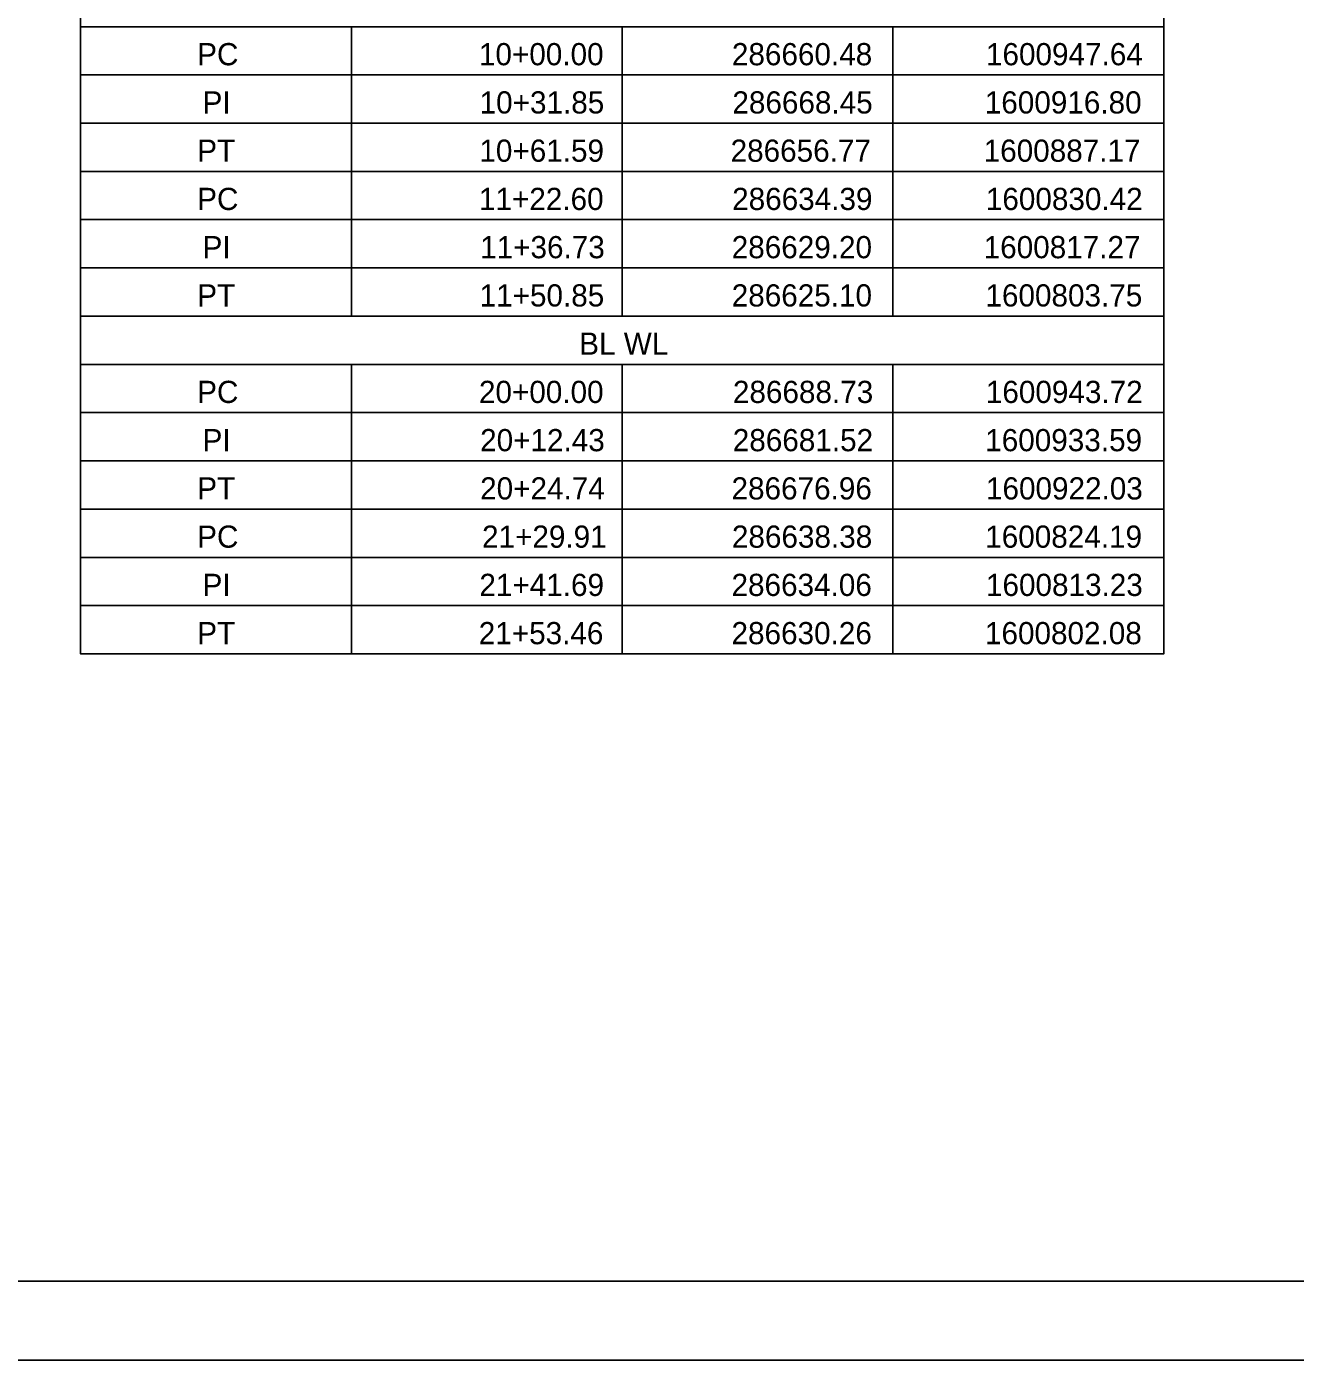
# Model space of a CAD drawing. Extents: x 0 to 34, y 0 to 22.
# Drawn here: x 17 to 25, y 0 to 8.41 of the extents above; entities that cross this region are included whole.
import ezdxf

# ---------------------------------------------------------------- set-up
doc = ezdxf.new("R2010")
doc.units = 0
for name, color, linetype in [('SH_Border', 7, 'Continuous'), ('SH_Cut_Line', 7, 'Continuous'), ('SH_Text', 7, 'Continuous')]:
    doc.layers.add(name, color=color, linetype=linetype)

msp = doc.modelspace()

# ---------------------------------------------------------------- linework, layer by layer
at = {"layer": 'SH_Border'}
msp.add_lwpolyline([(1.5, 21.5), (33.5, 21.5), (33.5, 0.5), (1.5, 0.5)], close=True, dxfattribs=at)
at = {"layer": 'SH_Cut_Line'}
msp.add_lwpolyline([(0, 0), (34, 0), (34, 22), (0, 22)], close=True, dxfattribs=at)
at = {"layer": 'SH_Text'}
for p, q in [((17.3382, 9.0217), (17.3382, 8.1087)), ((24.1691, 9.0217), (24.1691, 8.1087)), ((17.3382, 8.413), (24.1691, 8.413)), ((19.0459, 8.413), (19.0459, 8.1087)), ((20.7536, 8.413), (20.7536, 8.1087)), ((22.4614, 8.413), (22.4614, 8.1087)), ((17.3382, 8.1087), (24.1691, 8.1087)), ((17.3382, 8.1087), (17.3382, 7.8043)), ((19.0459, 8.1087), (19.0459, 7.8043)), ((20.7536, 8.1087), (20.7536, 7.8043)), ((22.4614, 8.1087), (22.4614, 7.8043)), ((24.1691, 8.1087), (24.1691, 7.8043)), ((17.3382, 7.8043), (24.1691, 7.8043)), ((17.3382, 7.8043), (17.3382, 7.1957)), ((19.0459, 7.8043), (19.0459, 7.1957)), ((20.7536, 7.8043), (20.7536, 7.1957)), ((22.4614, 7.8043), (22.4614, 7.1957)), ((24.1691, 7.8043), (24.1691, 7.1957)), ((17.3382, 7.5), (24.1691, 7.5)), ((17.3382, 7.1957), (24.1691, 7.1957)), ((17.3382, 7.1957), (17.3382, 6.8913)), ((19.0459, 7.1957), (19.0459, 6.8913)), ((20.7536, 7.1957), (20.7536, 6.8913)), ((22.4614, 7.1957), (22.4614, 6.8913)), ((24.1691, 7.1957), (24.1691, 6.8913)), ((17.3382, 6.8913), (24.1691, 6.8913)), ((17.3382, 6.8913), (17.3382, 5.9783)), ((19.0459, 6.8913), (19.0459, 6.587)), ((20.7536, 6.8913), (20.7536, 6.587)), ((22.4614, 6.8913), (22.4614, 6.587)), ((24.1691, 6.8913), (24.1691, 5.9783)), ((17.3382, 6.587), (24.1691, 6.587)), ((17.3382, 6.2826), (24.1691, 6.2826)), ((19.0459, 6.2826), (19.0459, 5.9783)), ((20.7536, 6.2826), (20.7536, 5.9783)), ((22.4614, 6.2826), (22.4614, 5.9783)), ((17.3382, 5.9783), (24.1691, 5.9783)), ((17.3382, 5.9783), (17.3382, 5.6739)), ((19.0459, 5.9783), (19.0459, 5.6739)), ((20.7536, 5.9783), (20.7536, 5.6739)), ((22.4614, 5.9783), (22.4614, 5.6739)), ((24.1691, 5.9783), (24.1691, 5.6739)), ((17.3382, 5.6739), (24.1691, 5.6739)), ((17.3382, 5.6739), (17.3382, 5.0652)), ((19.0459, 5.6739), (19.0459, 5.0652)), ((20.7536, 5.6739), (20.7536, 5.0652)), ((22.4614, 5.6739), (22.4614, 5.0652)), ((24.1691, 5.6739), (24.1691, 5.0652)), ((17.3382, 5.3696), (24.1691, 5.3696)), ((17.3382, 5.0652), (24.1691, 5.0652)), ((17.3382, 5.0652), (17.3382, 4.7609)), ((19.0459, 5.0652), (19.0459, 4.7609)), ((20.7536, 5.0652), (20.7536, 4.7609)), ((22.4614, 5.0652), (22.4614, 4.7609)), ((24.1691, 5.0652), (24.1691, 4.7609)), ((17.3382, 4.7609), (24.1691, 4.7609)), ((17.3382, 4.7609), (17.3382, 4.4565)), ((19.0459, 4.7609), (19.0459, 4.4565)), ((20.7536, 4.7609), (20.7536, 4.4565)), ((22.4614, 4.7609), (22.4614, 4.4565)), ((24.1691, 4.7609), (24.1691, 4.4565)), ((17.3382, 4.4565), (24.1691, 4.4565))]:
    msp.add_line(p, q, dxfattribs=at)
for points in [[(17.3382, 8.7174), (24.1691, 8.7174), (24.1691, 8.413), (17.3382, 8.413)], [(17.3382, 8.413), (19.0459, 8.413), (19.0459, 8.1087), (17.3382, 8.1087)], [(19.0459, 8.413), (20.7536, 8.413), (20.7536, 8.1087), (19.0459, 8.1087)], [(20.7536, 8.413), (22.4614, 8.413), (22.4614, 8.1087), (20.7536, 8.1087)], [(22.4614, 8.413), (24.1691, 8.413), (24.1691, 8.1087), (22.4614, 8.1087)], [(17.3382, 8.1087), (19.0459, 8.1087), (19.0459, 7.8043), (17.3382, 7.8043)], [(19.0459, 8.1087), (20.7536, 8.1087), (20.7536, 7.8043), (19.0459, 7.8043)], [(20.7536, 8.1087), (22.4614, 8.1087), (22.4614, 7.8043), (20.7536, 7.8043)], [(22.4614, 8.1087), (24.1691, 8.1087), (24.1691, 7.8043), (22.4614, 7.8043)], [(17.3382, 7.8043), (19.0459, 7.8043), (19.0459, 7.5), (17.3382, 7.5)], [(19.0459, 7.8043), (20.7536, 7.8043), (20.7536, 7.5), (19.0459, 7.5)], [(20.7536, 7.8043), (22.4614, 7.8043), (22.4614, 7.5), (20.7536, 7.5)], [(22.4614, 7.8043), (24.1691, 7.8043), (24.1691, 7.5), (22.4614, 7.5)], [(17.3382, 7.5), (19.0459, 7.5), (19.0459, 7.1957), (17.3382, 7.1957)], [(19.0459, 7.5), (20.7536, 7.5), (20.7536, 7.1957), (19.0459, 7.1957)], [(20.7536, 7.5), (22.4614, 7.5), (22.4614, 7.1957), (20.7536, 7.1957)], [(22.4614, 7.5), (24.1691, 7.5), (24.1691, 7.1957), (22.4614, 7.1957)], [(17.3382, 7.1957), (19.0459, 7.1957), (19.0459, 6.8913), (17.3382, 6.8913)], [(19.0459, 7.1957), (20.7536, 7.1957), (20.7536, 6.8913), (19.0459, 6.8913)], [(20.7536, 7.1957), (22.4614, 7.1957), (22.4614, 6.8913), (20.7536, 6.8913)], [(22.4614, 7.1957), (24.1691, 7.1957), (24.1691, 6.8913), (22.4614, 6.8913)], [(17.3382, 6.8913), (19.0459, 6.8913), (19.0459, 6.587), (17.3382, 6.587)], [(19.0459, 6.8913), (20.7536, 6.8913), (20.7536, 6.587), (19.0459, 6.587)], [(20.7536, 6.8913), (22.4614, 6.8913), (22.4614, 6.587), (20.7536, 6.587)], [(22.4614, 6.8913), (24.1691, 6.8913), (24.1691, 6.587), (22.4614, 6.587)], [(17.3382, 6.2826), (19.0459, 6.2826), (19.0459, 5.9783), (17.3382, 5.9783)], [(19.0459, 6.2826), (20.7536, 6.2826), (20.7536, 5.9783), (19.0459, 5.9783)], [(20.7536, 6.2826), (22.4614, 6.2826), (22.4614, 5.9783), (20.7536, 5.9783)], [(22.4614, 6.2826), (24.1691, 6.2826), (24.1691, 5.9783), (22.4614, 5.9783)], [(17.3382, 5.9783), (19.0459, 5.9783), (19.0459, 5.6739), (17.3382, 5.6739)], [(19.0459, 5.9783), (20.7536, 5.9783), (20.7536, 5.6739), (19.0459, 5.6739)], [(20.7536, 5.9783), (22.4614, 5.9783), (22.4614, 5.6739), (20.7536, 5.6739)], [(22.4614, 5.9783), (24.1691, 5.9783), (24.1691, 5.6739), (22.4614, 5.6739)], [(17.3382, 5.6739), (19.0459, 5.6739), (19.0459, 5.3696), (17.3382, 5.3696)], [(19.0459, 5.6739), (20.7536, 5.6739), (20.7536, 5.3696), (19.0459, 5.3696)], [(20.7536, 5.6739), (22.4614, 5.6739), (22.4614, 5.3696), (20.7536, 5.3696)], [(22.4614, 5.6739), (24.1691, 5.6739), (24.1691, 5.3696), (22.4614, 5.3696)], [(17.3382, 5.3696), (19.0459, 5.3696), (19.0459, 5.0652), (17.3382, 5.0652)], [(19.0459, 5.3696), (20.7536, 5.3696), (20.7536, 5.0652), (19.0459, 5.0652)], [(20.7536, 5.3696), (22.4614, 5.3696), (22.4614, 5.0652), (20.7536, 5.0652)], [(22.4614, 5.3696), (24.1691, 5.3696), (24.1691, 5.0652), (22.4614, 5.0652)], [(17.3382, 5.0652), (19.0459, 5.0652), (19.0459, 4.7609), (17.3382, 4.7609)], [(19.0459, 5.0652), (20.7536, 5.0652), (20.7536, 4.7609), (19.0459, 4.7609)], [(20.7536, 5.0652), (22.4614, 5.0652), (22.4614, 4.7609), (20.7536, 4.7609)], [(22.4614, 5.0652), (24.1691, 5.0652), (24.1691, 4.7609), (22.4614, 4.7609)], [(17.3382, 4.7609), (19.0459, 4.7609), (19.0459, 4.4565), (17.3382, 4.4565)], [(19.0459, 4.7609), (20.7536, 4.7609), (20.7536, 4.4565), (19.0459, 4.4565)], [(20.7536, 4.7609), (22.4614, 4.7609), (22.4614, 4.4565), (20.7536, 4.4565)], [(22.4614, 4.7609), (24.1691, 4.7609), (24.1691, 4.4565), (22.4614, 4.4565)]]:
    msp.add_lwpolyline(points, close=True, dxfattribs=at)

# ---------------------------------------------------------------- texts
for s, p in [('PC', (18.0734, 8.1696)), ('10+00.00', (19.8505, 8.1696)), ('286660.48', (21.4458, 8.1696)), ('1600947.64', (23.0481, 8.1696)), ('PI', (18.1078, 7.8652)), ('10+31.85', (19.8547, 7.8652)), ('286668.45', (21.4488, 7.8652)), ('1600916.80', (23.0406, 7.8652)), ('PT', (18.074, 7.5609)), ('10+61.59', (19.8532, 7.5609)), ('286656.77', (21.4376, 7.5609)), ('1600887.17', (23.0336, 7.5609)), ('PC', (18.0734, 7.2565)), ('11+22.60', (19.8505, 7.2565)), ('286634.39', (21.4474, 7.2565)), ('1600830.42', (23.0473, 7.2565)), ('PI', (18.1078, 6.9522)), ('11+36.73', (19.858, 6.9522)), ('286629.20', (21.4446, 6.9522)), ('1600817.27', (23.0336, 6.9522)), ('PT', (18.074, 6.6478)), ('11+50.85', (19.8547, 6.6478)), ('286625.10', (21.4446, 6.6478)), ('1600803.75', (23.0448, 6.6478)), ('BL WL', (20.4828, 6.3435)), ('PC', (18.0734, 6.0391)), ('20+00.00', (19.8505, 6.0391)), ('286688.73', (21.4521, 6.0391)), ('1600943.72', (23.0473, 6.0391)), ('PI', (18.1078, 5.7348)), ('20+12.43', (19.858, 5.7348)), ('286681.52', (21.4513, 5.7348)), ('1600933.59', (23.0434, 5.7348)), ('PT', (18.074, 5.4304)), ('20+24.74', (19.858, 5.4304)), ('286676.96', (21.4434, 5.4304)), ('1600922.03', (23.0481, 5.4304)), ('PC', (18.0734, 5.1261)), ('21+29.91', (19.87, 5.1261)), ('286638.38', (21.4458, 5.1261)), ('1600824.19', (23.0434, 5.1261)), ('21+41.69', (19.8532, 4.8217)), ('286634.06', (21.4434, 4.8217)), ('1600813.23', (23.0481, 4.8217)), ('PI', (18.1078, 4.8217)), ('PT', (18.074, 4.5174)), ('21+53.46', (19.8493, 4.5174)), ('286630.26', (21.4434, 4.5174)), ('1600802.08', (23.0418, 4.5174))]:
    msp.add_text(s, height=0.14, dxfattribs=at).set_placement(p)

doc.saveas('drawing.dxf')
